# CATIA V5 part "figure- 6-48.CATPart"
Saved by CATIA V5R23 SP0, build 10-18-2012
Part number: Part1
Bounding box of the stored display mesh (mm): x -40 to 40, y -70 to 70.325, z -50 to 50
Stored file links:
  D:\APS\CATIA V5-6R-2013-Project\CATIA V5-6R2013_partfiles\Part_Files\c06_catia_v5-6r2013_prt\figure- 6-48.CATPart
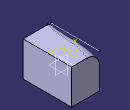
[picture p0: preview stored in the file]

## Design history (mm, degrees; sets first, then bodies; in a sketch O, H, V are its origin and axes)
Body1 (main body)
  Sketch1 on yz-plane, origin (0, 0, 0), H (0, 1, 0), V (0, 0, 1)
    line L1 (70, 50) -> (70, -50)
    line L2 (70, -50) -> (-70, -50)
    line L3 (-70, -50) -> (-70, 50)
    line L4 (-70, 50) -> (70, 50)
    length L1 = 100
    length L4 = 140
    vertical: L1 V, L3 V
    horizontal: L2 H, L4 H
    equidistance: L1 L3 O, L2 L4 O
  Pad1: profile Sketch1, direction (1, 0, 0), length 40, mirrored extent
  Sketch2 on face of Pad1 from Sketch1.L4, origin (0, 0, 50), H (1, 0, 0), V (0, 1, 0)
    spline S1 through (-30.7841, -70) (-23.8817, -36.0861) (-20.1722, 14.4073) (-10.2234, 55.7812) (-3.4223, 70.3253)
    reference projected line E1 (-40, -70) -> (40, -70) from edge [face of Pad1 from Sketch1.L3 | face of Pad1 from Sketch1.L4]
    point P1 (-30.7841, -70)
    coincidence: P1 E1
  Sketch3 on start face of Pad1, origin (-40, 0, 0), H (0, -1, 0), V (0, 0, 1)
    projected line E1 (-70.3253, 50) -> (70, 50) from Sketch2.S1
  FaceFillet1: ConicRatio 0.5, Face1 face of Pad1 from Sketch1.L4, Face2 start face of Pad1, HoldCurve Sketch2, Radius 5, Spine Sketch3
